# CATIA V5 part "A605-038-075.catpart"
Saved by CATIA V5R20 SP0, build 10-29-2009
Part number: A605-038-075
Source: Unknown
Property "A": "0.000"
Property "ARTICLENO": "A605-038-075"
Property "BOMINFO": "A605-038-075"
Property "CODE": "A605-038-075"
Property "D": "9.000"
Property "FORM": "A"
Property "L": "75.000"
Property "L1": "45.000"
Property "LINA": "A605-038-075"
Property "NB": "A605-038-075"
Property "NBSYN": "$CODE."
Property "NN": "A605"
Property "NT": "Wear Plates, self-lubricating"
Property "SCREW": "2*M8X16"
Property "SUPPLIER": "CF"
Property "W": "38.000"
Bounding box of the stored display mesh (mm): x -38 to 0, y 0 to 5, z -75 to 0
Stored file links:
  C:\Users\Utente\Desktop\3D files A605\A605-038-075.catpart
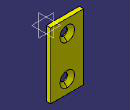
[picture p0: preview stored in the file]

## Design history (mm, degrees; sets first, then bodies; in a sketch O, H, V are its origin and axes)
Body1 "Geometry.1" (main body)
  Solid1 "A605-038-075.catpart": solid without history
